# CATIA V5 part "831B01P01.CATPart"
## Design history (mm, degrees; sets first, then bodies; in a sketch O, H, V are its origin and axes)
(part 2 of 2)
      symmetry: P1 P5 V, P2 P6 V, P3 P7 V, P4 P8 V, L1 L3 V, L2 L4 V, P9 P11 V, P10 P12 V, L5 L6 V, P13 P17 V, P14 P18 V, P15 P19 V, P16 P20 V, L7 L9 V, L8 L10 V
    Pad4: profile Sketch10, direction (0, 0, 1), length 9.5, thin wall 1.8
    Fillet1: radius 5, conic ratio 0.6, on edge [face of Pad4 | face of Pad4] (x10)
  Add1: tool Body2
  Align13: SewingRemoveFace face of Pocket4 from Sketch6.L53, SplitPlane face of Pocket5 from Sketch8.L69
  Align14: SewingRemoveFace face of Pocket4 from Sketch6.L50, SplitPlane face of Pocket5 from Sketch8.L75
  RemoveFace2: RemoveFaces (face of Pocket2; face of Pocket2; face of Pocket2; face of Pocket2; face of Pocket2; face of Pocket2; face of Pocket2; face of Pocket2; face of Pocket2; face of Pocket2)
  Thickness3: Face (face of Pocket2; face of Pocket2; face of Pocket2; face of Pocket2), Thickness -6
  Sketch11 on start face of Pad3, origin (0, 0, -6.5), H (1, 0, 0), V (0, 1, 0)
  Pad5: profile Sketch11, direction (0, 0, 1), up to face of Pocket2 from Sketch3.L2
  Thickness4: Face (face of Pocket4 from Sketch6.L13; face of Pocket4 from Sketch6.L13; face of Pocket4 from Sketch6.L13; face of Pocket4 from Sketch6.L9; face of Pocket4 from Sketch6.L9; face of Pocket4 from Sketch6.L9; face of Pocket4 from Sketch6.L42; face of Pocket4 from Sketch6.L17; face of Pocket4 from Sketch6.L17; face of Pocket4 from Sketch6.L17; face of Pocket4 from Sketch6.L42; face of Pocket4 from Sketch6.L42; face of Pocket4 from Sketch6.L38; face of Pocket4 from Sketch6.L38; face of Pocket4 from Sketch6.L38), Thickness 4
  Sketch12 on face of Pocket2, origin (0, 0, -2.5), H (1, 0, 0), V (0, 1, 0)
    projected line E1 (-41.5, 14) -> (-38, -14) from edge [face of Pocket4 | end face of Pad2]
    projected line E2 (-39.75, 0) -> (-38, -14) from edge [face of Pocket4 | end face of Pad2]
    projected line E3 (-60.5, 14) -> (-64, -14) from edge [end face of Pad2 | face of Pocket4]
    projected line E4 (-62.25, 0) -> (-64, -14) from edge [end face of Pad2 | face of Pocket4]
    projected line E5 (-13, -14) -> (-9.5, 14) from edge [face of Pocket4 | end face of Pad2]
    projected line E6 (-13, -14) -> (-11.25, 0) from edge [face of Pocket4 | end face of Pad2]
    projected line E7 (-16, -14) -> (-12.5, 14) from edge [end face of Pad2 | face of Pad2 from Sketch4.L10]
    projected line E8 (-14.25, 0) -> (-12.5, 14) from edge [end face of Pad2 | face of Pad2 from Sketch4.L10]
    projected line E9 (-38.5, 14) -> (-35, -14) from edge [end face of Pad2 | face of Pad2 from Sketch4.L11]
    projected line E10 (-38.5, 14) -> (-36.75, 0) from edge [end face of Pad2 | face of Pad2 from Sketch4.L11]
    projected line E11 (9.5, 14) -> (13, -14) from edge [face of Pocket4 | end face of Pad2]
    projected line E12 (11.25, 0) -> (13, -14) from edge [face of Pocket4 | end face of Pad2]
    projected line E13 (16, -14) -> (12.5, 14) from edge [face of Pad2 from Sketch4.L2 | end face of Pad2]
    projected line E14 (14.25, 0) -> (12.5, 14) from edge [face of Pad2 from Sketch4.L2 | end face of Pad2]
    projected line E15 (38.5, 14) -> (35, -14) from edge [face of Pad2 from Sketch4.L3 | end face of Pad2]
    projected line E16 (38.5, 14) -> (36.75, 0) from edge [face of Pad2 from Sketch4.L3 | end face of Pad2]
    projected line E17 (38, -14) -> (41.5, 14) from edge [face of Pocket4 | end face of Pad2]
    projected line E18 (38, -14) -> (39.75, 0) from edge [face of Pocket4 | end face of Pad2]
    projected line E19 (60.5, 14) -> (64, -14) from edge [face of Pocket4 | end face of Pad2]
    projected line E20 (62.25, 0) -> (64, -14) from edge [face of Pocket4 | end face of Pad2]
    construction line L1 (60.5, 14) -> (41.5, 14)
    line L2 (64, -14) -> (38, -14)
    line L3 (-38, -14) -> (-64, -14)
    construction line L4 (-41.5, 14) -> (-60.5, 14)
    line L5 (-12.5, 14) -> (-38.5, 14)
    construction line L6 (-16, -14) -> (-35, -14)
    line L7 (13, -14) -> (-13, -14)
    construction line L8 (35, -14) -> (16, -14)
    line L9 (38.5, 14) -> (12.5, 14)
    construction line L10 (9.5, 14) -> (-9.5, 14)
    line L11 (62.25, 0) -> (39.75, 0)
    line L12 (36.75, 0) -> (14.25, 0)
    line L13 (11.25, 0) -> (-11.25, 0)
    line L14 (-14.25, 0) -> (-36.75, 0)
    line L15 (-39.75, 0) -> (-62.25, 0)
    horizontal: L1 H, L2 H, L3 H, L4 H, L5 H, L6 H, L7 H, L8 H, L9 H, L10 H, L11 H, L12 H, L13 H, L14 H, L15 H
    coincidence: L2 L3, L1 L4, L1 L5, L2 L6, L2 L7, L2 L8, L1 L9, L9 L10, L11 L12, L12 L13, L13 L14, L14 L15
  Pocket7: profile Sketch12, direction (0, 0, 1), length 17.5
  Sketch13 on Plane2, origin (0, 0, 0), H (0, 1, 0), V (0, 0, 1)
    line L1 (-12.0329, -6.662) -> (-10.5651, -10.7484)
    line L2 (-10.5651, -10.7484) -> (-7.6933, -6.7897)
    line L3 (-7.6933, -6.7897) -> (-5.3959, -11.5145)
    line L4 (-5.3959, -11.5145) -> (-2.6517, -6.5343)
    line L5 (-2.6517, -6.5343) -> (2.0708, -12.7277)
    line L6 (2.0708, -12.7277) -> (4.8787, -6.5982)
    line L7 (4.8787, -6.5982) -> (7.7505, -13.2385)
    line L8 (7.7505, -13.2385) -> (11.4519, -6.5343)
Body3
  Solid1: linked copy from another document
  Translate1: Direction zx-plane, Length 38.1, ToTransfor Solid1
